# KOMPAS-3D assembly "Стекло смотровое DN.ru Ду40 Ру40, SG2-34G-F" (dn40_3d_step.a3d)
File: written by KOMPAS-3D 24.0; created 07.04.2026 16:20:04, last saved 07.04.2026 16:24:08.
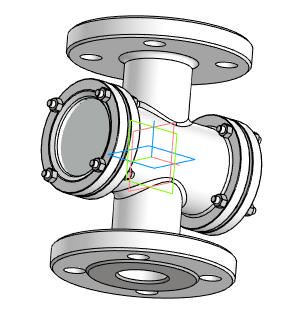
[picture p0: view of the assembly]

Document properties: Автор: Main; Полное имя файла: D:\DN.ru Аутсерс\Стекло смотровое DN.ru\Исходники\Стекло смотровое DN.ru SG2-34G-F тип В ГОСТ 21836-2021 Ду40 Ру40, углеродистая сталь, фланцевое\dn40_3d_step.a3d

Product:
- Component [detail]: Деталь  | qty 1  | pos. 1  | Масса: 7.155643; Автор: Main; additional columns: Типовые; source file: ДетальДеталь.m3d
- Component [detail]: Стекло  | qty 2  | pos. 2  | Масса: 0.138488; Автор: Main; source file: СтеклоСтекло.m3d
- Component [detail]: ANSI B18.2.4.2M - M6x1 - 10  | designation ANSI B18.2.4.2M - M6x1  | qty 16  | pos. 3  | Масса: 0.003008; Комментарий: Типы метрических   шестигранных гаек   2; Автор: Main; additional columns: Сталь, мягкая; source file: ANSI B18.2.4.2M - M6x1ANSI B18.2.4.2M - M6x1 - 10.m3d
- Part/product: Стекло смотровое DN.ru Ду40 Ру40  | designation SG2-34G-F
    Масса: 9
    Раздел спецификации: Прочие изделия
    Примечание: D500-00083

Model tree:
1. Массив по концентрической сетке:1  (labels: Грань.Твердое тело1; Ребро.Твердое тело1; Ребро.Solid1; Грань.Solid1)  (4 pattern instances)
     Шаг 2 = 360

Expressions: SG2-34G-F
Referenced files in D:\DN.ru Аутсерс\Стекло смотровое DN.ru\Исходники\Стекло смотровое DN.ru SG2-34G-F тип В ГОСТ 21836-2021 Ду40 Ру40, углеродистая сталь, фланцевое\: ДетальДеталь.m3d, СтеклоСтекло.m3d, ANSI B18.2.4.2M - M6x1ANSI B18.2.4.2M - M6x1 - 10.m3d
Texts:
  Стекло Стекло (1)
  Стекло Стекло (2)
  ANSI B18.2.4.2M - M6x1 ANSI B18.2.4.2M - M6x1 - 10 (1)
  ANSI B18.2.4.2M - M6x1 ANSI B18.2.4.2M - M6x1 - 10 (2)
  ANSI B18.2.4.2M - M6x1 ANSI B18.2.4.2M - M6x1 - 10 (3)
  ANSI B18.2.4.2M - M6x1 ANSI B18.2.4.2M - M6x1 - 10 (4)
  ANSI B18.2.4.2M - M6x1 ANSI B18.2.4.2M - M6x1 - 10 (5)
  ANSI B18.2.4.2M - M6x1 ANSI B18.2.4.2M - M6x1 - 10 (6)
  ANSI B18.2.4.2M - M6x1 ANSI B18.2.4.2M - M6x1 - 10 (7)
  ANSI B18.2.4.2M - M6x1 ANSI B18.2.4.2M - M6x1 - 10 (8)
  ANSI B18.2.4.2M - M6x1 ANSI B18.2.4.2M - M6x1 - 10 (9)
  ANSI B18.2.4.2M - M6x1 ANSI B18.2.4.2M - M6x1 - 10 (10)
  ANSI B18.2.4.2M - M6x1 ANSI B18.2.4.2M - M6x1 - 10 (11)
  ANSI B18.2.4.2M - M6x1 ANSI B18.2.4.2M - M6x1 - 10 (12)
  ANSI B18.2.4.2M - M6x1 ANSI B18.2.4.2M - M6x1 - 10 (13)
  ANSI B18.2.4.2M - M6x1 ANSI B18.2.4.2M - M6x1 - 10 (14)
  ANSI B18.2.4.2M - M6x1 ANSI B18.2.4.2M - M6x1 - 10 (15)
  ANSI B18.2.4.2M - M6x1 ANSI B18.2.4.2M - M6x1 - 10 (16)
  Ось Z.Начало координат
  Ось X.Начало координат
